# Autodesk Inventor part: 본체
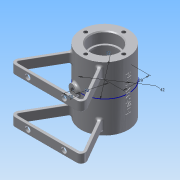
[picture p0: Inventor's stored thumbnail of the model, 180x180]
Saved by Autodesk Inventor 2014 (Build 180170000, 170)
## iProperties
Created: 2016-03
Part Number: 본체
Material: 알루미늄 6061
Document SubType Name: Modeling
Designer: net
Density: 2.71 g/cm^3
Appearance: 알루미늄 - 평지
Mass: 211.847 g
Surface Area: 336.045 cm^2
Volume: 78.1725 cm^3
Author: net
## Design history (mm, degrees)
sketch "스케치1"
  geometry: C1 r 26 at (0, 0); C2 r 21 at (0, 0); 1 further point
  constraints: 2 centre point, 2 coincident
  dimensions: "d0" = 52 diameter of C1; "d3" = 42 diameter of C2
extrude "돌출1" new body sketch "스케치1" stored distance "d1" = 70; taper "d2" = 0 deg
extrude "돌출2" cut sketch "스케치1" stored distance "d4" = 42; taper "d5" = 0 deg
hole "구멍1" diameter "d8" = 28; stored, may be unused: countersink angle "d12" = 90 deg, drill point angle "d14" = 118 deg; dims "d9" = 6, "d10" = 4, "d11" = 2, "d13" = 8, "d15" = 10, "d16" = 10
hole "구멍2" diameter "d19" = 32; stored, may be unused: countersink angle "d23" = 90 deg, drill point angle "d25" = 0 deg; dims "d17" = 10, "d18" = 10, "d20" = 6, "d21" = 4, "d22" = 2, "d24" = 12
node "작업 평면1"
fillet "모깎기1" dims "d26" = 0.3, "d27" = 3
chamfer "모따기1" distance "d28" = 1; stored, may be unused: second distance "d29" = 2, angle "d30" = 45 deg
node "작업 평면2"
sketch "스케치4"
  geometry: L1 (33.934, -65)-(-33.934, -65); L2 (-38.264, -57.5)-(-16.613, -20); L3 (38.264, -57.5)-(16.613, -20); L4 (0, -65)-(0, 0); L5 (-14.183, -21.791)-(-35.666, -59); L6 (-33.934, -62)-(33.934, -62); L7 (35.666, -59)-(14.183, -21.791); C1 r 17 at (0, 0) reference; A1 r 26 centre (0, 0) between (-16.613, -20) and (16.613, -20) reference; A2 r 5 centre (33.934, -60) between (33.934, -65) and (38.264, -57.5); A3 r 5 centre (-33.934, -60) between (-38.264, -57.5) and (-33.934, -65); A4 r 2 centre (-33.934, -60) between (-35.666, -59) and (-33.934, -62); A5 r 2 centre (33.934, -60) between (33.934, -62) and (35.666, -59); 1 further point
  constraints: 14 end point, 12 point on circle, 4 centre point, 4 tangent, 1 coincident, 1 equal radius, 1 horizontal, 1 midpoint, 1 vertical alignment, 2 other
  dimensions: "d35" = 65 distance from line of L1 point (0, 0); "d38" = 45 distance from line of L1 L2.end; "d39" = 30 deg angle of L3 L4; "d40" = 30 deg angle of L2 L4; "d41" = 5 radius of A2; "d42" = 3 distance between parallel lines of L1 L6; "d43" = 3 distance between parallel lines of L2 L5; "d44" = 3 distance between parallel lines of L3 L7
extrude "돌출3" join sketch "스케치4" distance "d45" = 10; taper "d46" = 0 deg
sketch "스케치5"
  geometry: L1 (0, 0)-(0, 29); L2 (0, 0)-(-7.506, -28.012); L3 (0, 0)-(0, -26); L4 (0, 0)-(26, 0); A1 r 26 centre (0, 0) between (0, -26) and (26, 0) reference
  constraints: 8 end point, 2 point on circle, 2 vertical alignment, 1 horizontal alignment
  dimensions: "d47" = 29 distance of L1.start L1.end; "d53" = 29 distance of L1.start L2.end; "d54" = 15 deg angle of L3 L2
node "작업 평면3"
sketch "스케치6"
  geometry: C1 r 5 at (0, 0); 1 further point
  constraints: 1 centre point, 1 coincident
  dimensions: "d48" = 10 diameter of C1
extrude "돌출4" join sketch "스케치6" stored distance "d49" = 10; taper "d50" = 0 deg
node "작업 평면4"
sketch "스케치8"
  geometry: C1 r 6 at (0, 0); 1 further point
  constraints: 1 centre point, 1 coincident
  dimensions: "d55" = 12 diameter of C1
extrude "돌출5" join sketch "스케치8" stored distance "d56" = 10; taper "d57" = 0 deg
node "작업 평면5"
sketch "스케치10"
  geometry: 2 further points
  constraints: 1 coincident, 1 other
feature "엠보싱1" sketch "스케치10" dims "d58" = 0.5, "d59" = 0
sketch "스케치12"
  geometry: L1 (67.868, 10)-(0, 10) reference; L2 (33.934, 5)-(33.934, -45); L3 (67.868, -50)-(0, -50) reference; L4 (13.934, 5)-(13.934, -45); L5 (53.934, 5)-(53.934, -45); 2 further points
  constraints: 6 end point, 2 parallel, 2 vertical alignment, 1 midpoint
  dimensions: "d60" = 5 distance from line of L3 L2.end; "d61" = 5 distance from line of L2.start L1; "d62" = 20 distance between parallel lines of L2 L4; "d63" = 20 distance from line of L5.end L2
hole "구멍3" sketch "스케치12" at (13.934, 5) diameter "d64" = 6; stored, may be unused: countersink angle "d68" = 90 deg, drill point angle "d70" = 0 deg; dims "d65" = 6, "d66" = 4, "d67" = 2, "d69" = 12
fillet "모깎기2" dims "d77" = 0.5
fillet "모깎기3" dims "d78" = 3
sketch "스케치13" dims "d79" = 42
  geometry: L1 (0, 0)-(0, 21); C1 r 26 at (0, 0) reference; C2 r 17 at (0, 0) reference
  constraints: 2 end point, 2 vertical alignment, 2 other
hole "구멍4" sketch "스케치13" at (0, 21) diameter "d80" = 4; stored, may be unused: countersink angle "d84" = 90 deg, drill point angle "d86" = 118 deg; dims "d81" = 6, "d82" = 4, "d83" = 2, "d85" = 10
feature "스레드1" dims "d90" = 8, "d91" = 0
feature "스레드2" dims "d92" = 8, "d93" = 0
feature "스레드3" dims "d94" = 8, "d95" = 0
feature "스레드4" dims "d96" = 8, "d97" = 0
feature "스레드5" dims "d98" = 8, "d99" = 0
feature "스레드6" dims "d100" = 8, "d101" = 0
feature "스레드7" dims "d102" = 8, "d103" = 0
feature "스레드8" dims "d104" = 8, "d105" = 0
fillet "모깎기4" dims "d106" = 2
hole "구멍5" diameter "d109" = 6; stored, may be unused: countersink angle "d113" = 90 deg, drill point angle "d115" = 0 deg; dims "d107" = 10, "d108" = 10, "d110" = 6, "d111" = 4, "d112" = 2, "d114" = 10
hole "구멍6" diameter "d118" = 6; stored, may be unused: countersink angle "d122" = 90 deg, drill point angle "d124" = 0 deg; dims "d116" = 10, "d117" = 10, "d119" = 6, "d120" = 4, "d121" = 2, "d123" = 10
feature "스레드9" dims "d125" = 10, "d126" = 0
feature "스레드10" dims "d127" = 10, "d128" = 0
node "솔리드1"
mirror "대칭1"
mirror "대칭2"
pattern_linear "직사각형 패턴1" dims "d73" = -40
pattern_circular "원형 패턴1" dims angle "d88" = 360 deg
mirror "대칭3"
node "투영된 루프1"
